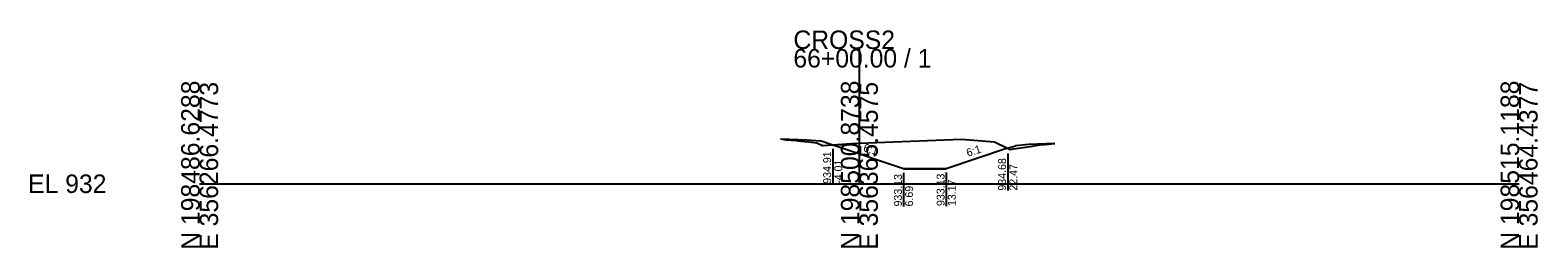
# Model space of a CAD drawing. Extents: x -26 to 203, y -10 to 14021.
# Drawn here: x -25.7 to 202.8, y 6990.3 to 7023.2 of the extents above; entities that cross this region are included whole.
import ezdxf

# ---------------------------------------------------------------- set-up
doc = ezdxf.new("R2010")
doc.units = 0
for name, color, linetype in [('Default', 7, 'Continuous'), ('P_E_XS_Ground', 7, 'Continuous'), ('P_XS', 7, 'Continuous'), ('P_XS_EAR_CommonGrnd', 7, 'Continuous'), ('P_XS_Lane', 7, 'Continuous'), ('P_XS_Rock', 7, 'Continuous')]:
    doc.layers.add(name, color=color, linetype=linetype)

msp = doc.modelspace()

# ---------------------------------------------------------------- linework, layer by layer
at = {"layer": 'Default'}
for p, q in [((100, 7000), (100, 7020.38)), ((0, 7000), (100, 7000)), ((100, 7000), (200, 7000))]:
    msp.add_line(p, q, dxfattribs=at)
at = {"layer": 'P_E_XS_Ground'}
for p, q in [((88.05, 7006.79), (88.91, 7006.64)), ((88.91, 7006.64), (90.43, 7006.55)), ((90.43, 7006.55), (91.14, 7006.46)), ((91.14, 7006.46), (92.31, 7006.32)), ((92.31, 7006.32), (93.54, 7006.19)), ((93.54, 7006.19), (94.5, 7005.71)), ((99.5, 7006.11), (94.5, 7005.71)), ((99.5, 7006.11), (100, 7006.13)), ((100, 7006.13), (115.5, 7006.75)), ((115.5, 7006.75), (120.5, 7006.35)), ((120.5, 7006.35), (122.85, 7005.17)), ((122.85, 7005.17), (123.39, 7005.3)), ((123.39, 7005.3), (125.87, 7005.63)), ((125.87, 7005.63), (127.07, 7005.82)), ((127.07, 7005.82), (127.63, 7005.92)), ((127.63, 7005.92), (128.17, 7005.93)), ((128.17, 7005.93), (129.65, 7006.07))]:
    msp.add_line(p, q, dxfattribs=at)
at = {"layer": 'P_XS'}
for p, q in [((88.05, 7006.79), (92.05, 7006.63)), ((92.05, 7006.63), (94.05, 7006.47)), ((95.99, 7005.83), (94.05, 7006.47)), ((122.47, 7005.36), (123.65, 7005.75)), ((125.65, 7005.91), (123.65, 7005.75)), ((129.65, 7006.07), (125.65, 7005.91))]:
    msp.add_line(p, q, dxfattribs=at)
at = {"layer": 'P_XS_EAR_CommonGrnd'}
msp.add_lwpolyline([(100, 7006.13), (115.5, 7006.75), (120.5, 7006.35), (122.47, 7005.36), (113.17, 7002.26), (106.69, 7002.26), (95.99, 7005.83), (99.5, 7006.11)], close=True, dxfattribs=at)
at = {"layer": 'P_XS_Lane'}
for p, q in [((106.69, 7002.26), (95.99, 7005.83)), ((122.47, 7005.36), (113.17, 7002.26)), ((106.69, 7002.26), (113.17, 7002.26))]:
    msp.add_line(p, q, dxfattribs=at)
at = {"layer": 'P_XS_Rock'}
for p, q in [((95.96, 7005.3), (95.96, 6999.99)), ((122.48, 7004.55), (122.48, 6998.96)), ((106.69, 7001.67), (106.69, 6996.56)), ((113.16, 7001.72), (113.16, 6996.62))]:
    msp.add_line(p, q, dxfattribs=at)

# ---------------------------------------------------------------- texts
at = {"layer": 'Default'}
for s, p in [('CROSS2', (90, 7020.38)), ('66+00.00 / 1', (90, 7017.58)), ('EL 932', (-26, 6998.6))]:
    msp.add_text(s, height=2.8, dxfattribs=at).set_placement(p)
for s, p in [('N 198486.6288', (0, 6990)), ('E 356266.4773', (2.8, 6990)), ('N 198500.8738', (100, 6990)), ('E 356365.4575', (102.8, 6990)), ('N 198515.1188', (200, 6990)), ('E 356464.4377', (202.8, 6990))]:
    msp.add_text(s, height=2.8, rotation=90, dxfattribs=at).set_placement(p)
at = {"layer": 'P_XS_Rock'}
for s, rotation, p in [('934.91', 90, (95.71, 6999.99)), ('6:1', 341.5651, (100.49, 7004.98)), ('6:1', 18.4349, (116.45, 7004.05)), ('-4.01', 90, (97.41, 6999.99)), ('934.68', 90, (122.23, 6998.96)), ('22.47', 90, (123.93, 6998.96)), ('933.13', 90, (106.44, 6996.56)), ('933.13', 90, (112.91, 6996.62)), ('13.17', 90, (114.61, 6996.62)), ('6.69', 90, (108.14, 6996.56))]:
    msp.add_text(s, height=1.2, rotation=rotation, dxfattribs=at).set_placement(p)

doc.saveas('drawing.dxf')
